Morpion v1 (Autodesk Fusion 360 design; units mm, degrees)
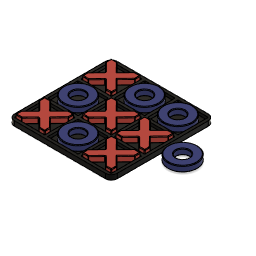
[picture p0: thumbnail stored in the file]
parameter "d1" = 265.687
sketch "Esquisse" plane through (0, 0, 0) normal (0, 1, 0) x axis (1, 0, 0)
  line L1 (54, 34) -> (-122, 34)
  line L2 (54, -142) -> (54, 34)
  line L3 (-122, -142) -> (54, -142)
  line L4 (-122, 34) -> (-122, -142)
  line L5 (-65, -142) -> (-65, 34)
  line L6 (-60, -142) -> (-60, 34)
  line L7 (-8, -142) -> (-8, 34)
  line L8 (-3, -142) -> (-3, 34)
  line L9 (54, -23) -> (-122, -23)
  line L10 (54, -28) -> (-122, -28)
  line L11 (54, -80) -> (-122, -80)
  line L12 (54, -85) -> (-122, -85)
  line L13 (54, 29) -> (-122, 29)
  line L14 (-117, -142) -> (-117, 34)
  line L15 (49, -145.687) -> (49, 34)
  line L16 (54, -137) -> (-122, -137)
  line L17 (-106, 28) -> (-116, 28)
  line L18 (-116, 18) -> (-116, 28)
  line L19 (-76, 28) -> (-66, 28)
  line L20 (-66, 28) -> (-76, 28)
  line L21 (-66, 18.5) -> (-66, 28)
  line L22 (-66, -12.5) -> (-66, -22)
  line L23 (-76, -22) -> (-66, -22)
  line L24 (-105.5122, -22) -> (-116, -22)
  line L25 (-116, -12.5) -> (-116, -22)
  line L26 (-100.8447, 2.8447) -> (-116, -12.5)
  line L27 (-76, 28) -> (-91, 12.8125)
  line L28 (-100.8447, 2.8447) -> (-116, 18)
  line L29 (-76, -22) -> (-90.9383, -7.0617)
  line L30 (-91, 12.8125) -> (-106, 28)
  line L31 (-66, -12.5) -> (-81.2147, 2.9049)
  line L32 (-90.9383, -7.0617) -> (-105.5122, -22)
  line L33 (-66, 18.5) -> (-81.2147, 2.9049)
  line L34 (-8, -23) -> (-60, 29)
  line L35 (-60, -23) -> (-8, 29)
  circle C1 centre (-34, 3) radius 25
  circle C2 centre (-34, 3) radius 11.2
  point P6 (-65, 34)
  point P7 (-65, -142)
  point P8 (-60, 34)
  point P9 (-60, -142)
  point P10 (-8, 34)
  point P11 (-8, -142)
  point P12 (-3, 34)
  point P13 (-3, -142)
  point P14 (-122, -23)
  point P15 (54, -23)
  point P16 (-122, -28)
  point P17 (54, -28)
  point P18 (-122, -80)
  point P19 (54, -80)
  point P20 (-122, -85)
  point P21 (54, -85)
  point P23 (54, 29)
  point P24 (-117, 34)
  point P25 (-117, -142)
  point P26 (49, 34)
  point P28 (-122, -137)
  point P29 (54, -137)
  point P22 (-122, 29)
  point P45 (-81.2147, 2.9049)
  point P46 (-60, 29)
  point P47 (-8, -23)
  point P48 (-8, 29)
  point P49 (-60, -23)
  point P50 (-34, 3)
  horizontal L1
  vertical L2
  horizontal L3
  vertical L4
  coincident L1 P6
  coincident L3 P7
  perpendicular L3 L5
  coincident L1 P8
  coincident L3 P9
  perpendicular L3 L6
  coincident L1 P10
  coincident L3 P11
  perpendicular L3 L7
  coincident L1 P12
  coincident L3 P13
  perpendicular L1 L8
  coincident L4 P14
  coincident L2 P15
  perpendicular L2 L9
  coincident L4 P16
  coincident L2 P17
  perpendicular L2 L10
  coincident L4 P18
  coincident L2 P19
  perpendicular L2 L11
  coincident L4 P20
  coincident L2 P21
  perpendicular L2 L12
  coincident L2 P23
  perpendicular L2 L13
  coincident L1 P24
  coincident L3 P25
  perpendicular L3 L14
  coincident L1 P26
  perpendicular L11 L15
  coincident L4 P28
  coincident L2 P29
  perpendicular L2 L16
  coincident L4 P22
  perpendicular L14 L17
  perpendicular L17 L18
  parallel L13 L19
  perpendicular L19 L21
  perpendicular L9 L22
  perpendicular L22 L23
  perpendicular L14 L24
  perpendicular L24 L25
  collinear L26 L27
  collinear L28 L29
  coincident P45 L32
  collinear L30 L31
  collinear L32 L33
  coincident L13 P46
  coincident L6 P46
  coincident L7 P47
  coincident L9 P47
  coincident L7 P48
  coincident L13 P48
  coincident L9 P49
  coincident L6 P49
  midpoint L35 P50
  concentric C1 C2
  dimension "d3" distance L5 L6 = 5
  dimension "d4" distance L7 L8 = 5 (= "d3")
  dimension "d5" distance L9 L10 = 5 (= "d3")
  dimension "d6" distance L11 L12 = 5 (= "d3")
  dimension "d7" distance L1 L13 = 5 (= "d3")
  dimension "d8" distance L2 L15 = 5 (= "d3")
  dimension "d9" distance L4 L14 = 5 (= "d3")
  dimension "d10" distance L3 L16 = 5 (= "d3")
  dimension "d11" distance L5 L14 = 52
  dimension "d12" distance L9 L13 = 52 (= "d11")
  dimension "d13" distance L10 L11 = 52 (= "d11")
  dimension "d14" distance L12 L16 = 52 (= "d11")
  dimension "d15" distance L6 L7 = 52 (= "d11")
  dimension "d16" distance L8 L15 = 52 (= "d11")
  dimension "d17" distance L5 L22 = 1
  dimension "d18" distance L5 L21 = 1 (= "d17")
  dimension "d19" distance L13 L19 = 1 (= "d17")
  dimension "d20" distance L14 L18 = 1 (= "d17")
  dimension "d21" distance L14 L25 = 1 (= "d17")
  dimension "d22" distance C1 C2 = 13.8
  dimension "d23" diameter C1 = 50
  dimension "d24" distance L9 L24 = 1 (= "d17")
  dimension "d25" distance L9 L23 = 1 (= "d17")
extrude "Extrusion1" new body sketch "Esquisse" profile of L1 L2 L3 L4 L5 L6 L7 L8 L9 L10 L11 L12 L13 L14 L15 L16 along normal blind 5 bodies "Plateau"
extrude "Extrusion2" add sketch "Esquisse" profile of L1 L2 L3 L4 L5 L6 L7 L8 L9 L10 L11 L12 L13 L14 L15 L16 L17 L18 L19 L20 L21 L22 L23 L24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 against normal blind 3
extrude "Extrusion3" new body sketch "Esquisse" profile of L17 L18 L19 L20 L21 L22 L23 L24 L25 L29 L31 L27 L33 along normal blind 10
extrude "Extrusion4" new body sketch "Esquisse" profile of C1 C2 along normal blind 10 bodies "Rond"
fillet "Congé1" radius 10
fillet "Congé2" radius 1
fillet "Congé4" radius 1
fillet "Congé5" radius 1
copy_paste_bodies "Copier/Coller des corps1"
move "Déplacer1"
copy_paste_bodies "Copier/Coller des corps2"
move "Déplacer2"
copy_paste_bodies "Copier/Coller des corps3"
move "Déplacer3"
copy_paste_bodies "Copier/Coller des corps4"
move "Déplacer4"
copy_paste_bodies "Copier/Coller des corps5"
move "Déplacer5"
copy_paste_bodies "Copier/Coller des corps6"
move "Déplacer6"
copy_paste_bodies "Copier/Coller des corps7"
move "Déplacer7"
copy_paste_bodies "Copier/Coller des corps8"
move "Déplacer8"
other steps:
base_feature "Fonction de base1" bodies "Croix", "Croix (1)"
base_feature "Fonction de base2" bodies "Croix (1)", "Croix (1) (1)"
base_feature "Fonction de base3" bodies "Rond", "Rond (1)"
base_feature "Fonction de base4" bodies "Rond (1)", "Rond (1) (1)"
base_feature "Fonction de base5" bodies "Croix (2)"
base_feature "Fonction de base6" bodies "Rond (2)"
base_feature "Fonction de base7" bodies "Croix (3)"
base_feature "Fonction de base8" bodies "Rond (3)"
named bodies: "Plateau", "Croix", "Rond", "Croix (1)", "Croix (1) (1)", "Rond (1)", "Rond (1) (1)", "Croix (2)", "Rond (2)", "Croix (3)", "Rond (3)"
